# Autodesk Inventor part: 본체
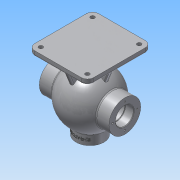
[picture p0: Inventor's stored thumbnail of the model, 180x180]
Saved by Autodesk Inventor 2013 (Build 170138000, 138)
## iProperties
Created: 2018-06
Part Number: 본체
Material: 알루미늄 6061
Document SubType Name: Modeling
Designer: Administrator
Density: 2.71 g/cm^3
Mass: 1508.48 g
Surface Area: 1156.61 cm^2
Volume: 556.635 cm^3
Author: Administrator
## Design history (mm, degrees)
sketch "스케치5"
  geometry: L1 (-53, 0)-(53, 0); A1 r 53 centre (0, 0) between (53, 0) and (-53, 0); A2 r 43 centre (0, 0) between (43, 0) and (-43, 0); 2 further points
  constraints: 4 point on circle, 3 coincident, 2 centre point, 2 end point, 2 point on line, 1 horizontal, 1 midpoint
  dimensions: "d19" = 106 diameter of A1; "d20" = 86 diameter of A2
revolve "회전2" sketch "스케치5" stored, may be unused: angle "d21" = 90 deg
sketch "스케치6"
  geometry: L1 (53, 0)-(68, 0); L2 (68, 0)-(68, 31); L3 (68, 31)-(42.988, 31); C1 r 43 at (0, 0) reference; A1 r 53 centre (0, 0) between (42.988, 31) and (53, 0) reference; 1 further point
  constraints: 6 end point, 2 point on circle, 1 horizontal, 1 parallel, 1 point on line, 1 vertical
  dimensions: "d22" = 62 diameter of L2.end L1; "d24" = 68 distance from line of L2 point (0, 0)
revolve "회전3" sketch "스케치6" stored, may be unused: angle "d25" = 90 deg
sketch "스케치9"
  geometry: L1 (68, -31)-(68, 31) reference; L2 (43, 0)-(68, 0); L3 (68, 0)-(68, 17.5); L4 (68, 17.5)-(52, 17.5); L5 (52, 17.5)-(52, 18.5); L6 (52, 18.5)-(50.25, 18.5); L7 (50.25, 18.5)-(50.25, 17.5); L8 (50.25, 17.5)-(39.278, 17.5); A1 r 43 centre (0, 0) between (43, 0) and (39.278, 17.5) reference; 1 further point
  constraints: 14 end point, 2 collinear, 2 parallel, 2 perpendicular, 2 point on circle, 2 point on line, 1 midpoint
  dimensions: "d27" = 35 diameter of L3.end L2; "d136" = 16 distance of L3.end L4.end; "d137" = 1.75 distance between parallel lines of L5 L7; "d138" = 37 diameter of L5.end L2; "d139" = 35 diameter of L7.end L2
revolve "회전4" sketch "스케치9" stored, may be unused: angle "d31" = 90 deg
sketch "스케치12"
  geometry: C1 r 31 at (0, 0) reference; C2 r 17.5 at (0, 0)
  constraints: 1 centre point, 1 coincident
  dimensions: "d36" = 35 diameter of C2
extrude "돌출1" cut sketch "스케치12" stored distance "d37" = 10; taper "d38" = 0 deg
sketch "스케치14"
  geometry: C1 r 31 at (0, 0) reference; 1 further point
  constraints: 1 vertical alignment
  dimensions: "d44" = 22.5 distance of point (0, 22.5) C1.centre
hole "구멍1" sketch "스케치14" at (0, 22.5) diameter "d45" = 3.242; stored, may be unused: countersink angle "d49" = 90 deg, drill point angle "d51" = 118 deg; dims "d46" = 12, "d47" = 35, "d48" = 16, "d50" = 15
sketch "스케치15"
  geometry: C1 r 31 at (0, 0) reference; 1 further point
  constraints: 1 vertical alignment
  dimensions: "d56" = 24 distance of C1.centre point (0, 24)
hole "구멍2" sketch "스케치15" at (0, 24) diameter "d57" = 3.242; stored, may be unused: countersink angle "d61" = 90 deg, drill point angle "d63" = 118 deg; dims "d58" = 16, "d59" = 35, "d60" = 16, "d62" = 19
node "작업 평면2"
sketch "스케치16"
  geometry: C1 r 27 at (0, 0); 1 further point
  constraints: 1 centre point, 1 coincident
  dimensions: "d68" = 54 diameter of C1
extrude "돌출2" join sketch "스케치16" stored distance "d69" = 54 (= d68); taper "d70" = 0 deg
sketch "스케치17"
  geometry: C1 r 27 at (0, 0) reference; C2 r 13 at (0, 0)
  constraints: 1 centre point, 1 coincident
  dimensions: "d71" = 26 diameter of C2
extrude "돌출3" cut sketch "스케치17" stored distance "d72" = 10; taper "d73" = 0 deg
sketch "스케치18"
  geometry: C1 r 13 at (0, 0) reference; 1 further point
  constraints: 1 vertical alignment
  dimensions: "d74" = 20 distance of C1.centre point (0, 20)
hole "구멍3" sketch "스케치18" at (0, 20) diameter "d75" = 3.242; stored, may be unused: countersink angle "d79" = 90 deg, drill point angle "d81" = 118 deg; dims "d76" = 9, "d77" = 35, "d78" = 16, "d80" = 11
chamfer "모따기4" distance "d88" = 1; stored, may be unused: second distance "d89" = 2, angle "d90" = 45 deg
fillet "모깎기1" dims "d91" = 3
sketch "스케치19"
  geometry: L1 (57.5, 75)-(-57.5, 75); L2 (-57.5, 75)-(-57.5, 85); L3 (-57.5, 85)-(57.5, 85); L4 (57.5, 85)-(57.5, 75); 2 further points
  constraints: 8 end point, 2 parallel, 1 horizontal, 1 midpoint, 1 perpendicular, 1 vertical alignment
  dimensions: "d92" = 115 distance of L2.end L3.end; "d93" = 10 distance of L1.end L2.end; "d94" = 85 distance from line of point (0, 0) L3
extrude "돌출4" join sketch "스케치19" stored distance "d95" = 125; taper "d96" = 0 deg
sketch "스케치20"
  geometry: L1 (0, 0)-(115, 0) reference; L2 (61.5, -115)-(53.5, -115); L3 (53.5, -115)-(53.5, -10); L4 (53.5, -10)-(61.5, -10); L5 (61.5, -10)-(61.5, -115); L6 (61.5, -115)-(53.5, -10); L7 (53.5, -115)-(61.5, -10); 1 further point
  constraints: 12 end point, 2 midpoint, 2 parallel, 1 horizontal, 1 perpendicular
  dimensions: "d97" = 10 distance between parallel lines of L1 L4; "d98" = 8 distance of L3.end L4.end
extrude "돌출5" join sketch "스케치20" stored distance "d99" = 125; taper "d100" = 0 deg
feature "면 기울기1" dims angle "d101" = 22 deg
sketch "스케치21"
  geometry: L1 (-47.5, 75)-(-39.576, 55.388); L2 (57.5, 75)-(-57.5, 75) reference; L3 (-57.5, 75)-(-57.5, 85) reference; 1 further point
  constraints: 2 end point, 1 point on line
  dimensions: "d102" = 22 deg angle of L1 L3; "d103" = 10 distance from line of L1.start L3
feature "리브1" sketch "스케치21" dims "d104" = 1, "d105" = 8, "d106" = 0, "d107" = 0, "d108" = 1, "d109" = 1
node "작업 평면3"
sketch "스케치22"
  geometry: L1 (27, 0)-(27, 17.714) reference; L2 (27, 0)-(-27, 0) reference; 2 further points
  constraints: 1 other
  dimensions: "d110" = 27 distance from line of point (0, 10) L1; "d111" = 10 distance from line of L2 point (0, 10)
feature "엠보싱1" sketch "스케치22" dims "d112" = 0.5, "d113" = 0
fillet "모깎기2" dims "d114" = 3
fillet "모깎기3" dims "d115" = 3
fillet "모깎기4" dims "d116" = 12
sketch "스케치24"
  geometry: A1 r 12 centre (91, -113) between (91, -125) and (103, -113) reference; A2 r 12 centre (91, -12) between (103, -12) and (91, 0) reference; A3 r 12 centre (0, -12) between (0, 0) and (-12, -12) reference; A4 r 12 centre (0, -113) between (-12, -113) and (0, -125) reference; 5 further points
  constraints: 4 coincident
hole "구멍4" sketch "스케치24" at (0, -12), (91, -12), (91, -113), (0, -113) diameter "d122" = 8; stored, may be unused: countersink angle "d126" = 90 deg, drill point angle "d128" = 118 deg; dims "d123" = 9, "d124" = 12, "d125" = 3, "d127" = 11
fillet "모깎기5" dims "d129" = 3
chamfer "모따기5" distance "d143" = 1; stored, may be unused: second distance "d144" = 2, angle "d145" = 45 deg
node "솔리드2"
mirror "대칭1"
pattern_circular "원형 패턴1" dims angle "d53" = 360 deg
pattern_circular "원형 패턴3" dims angle "d83" = 360 deg
mirror "대칭2"
pattern_circular "원형 패턴4" dims angle "d141" = 360 deg
other parameters: "d67" = -65
